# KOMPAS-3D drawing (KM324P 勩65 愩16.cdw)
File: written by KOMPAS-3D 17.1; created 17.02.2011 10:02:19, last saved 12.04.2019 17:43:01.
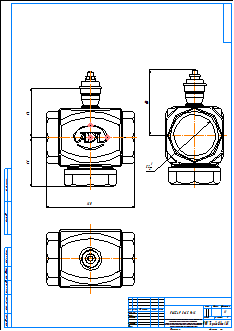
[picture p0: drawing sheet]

Title block, sheet 1: name: KM324P Ду65 Ру16; material: Внимание! Данный продукт является объектом авторского права ООО «Торговый Дом АДЛ». / Запрещается изменение, копирование, распространение / (в том числе путем копирования на другие сайты и ресурсы в Интернете) / или любое иное использование информации и объектов без предварительного / согласия правообладателя (ООО «Торговый Дом АДЛ»).; scale: 1:1; sheets: 1; organisation: ООО "Торговый дом АДЛ"; sheet format: A2; stored path: \\adlc.lan\data\АДЛ_ПКД\3D-модели\ADL production\Клапаны ГРАНРЕГ\Трёхходовой клапан KM324P\KOMPAS 2D\KM324P Ду65 Ру16.cdw

Views: Спереди 1, Проекционный вид 2, Проекционный вид 3
Dimensions and other numbers on the sheet: 89; 84; 113; 160; 1:1; 1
